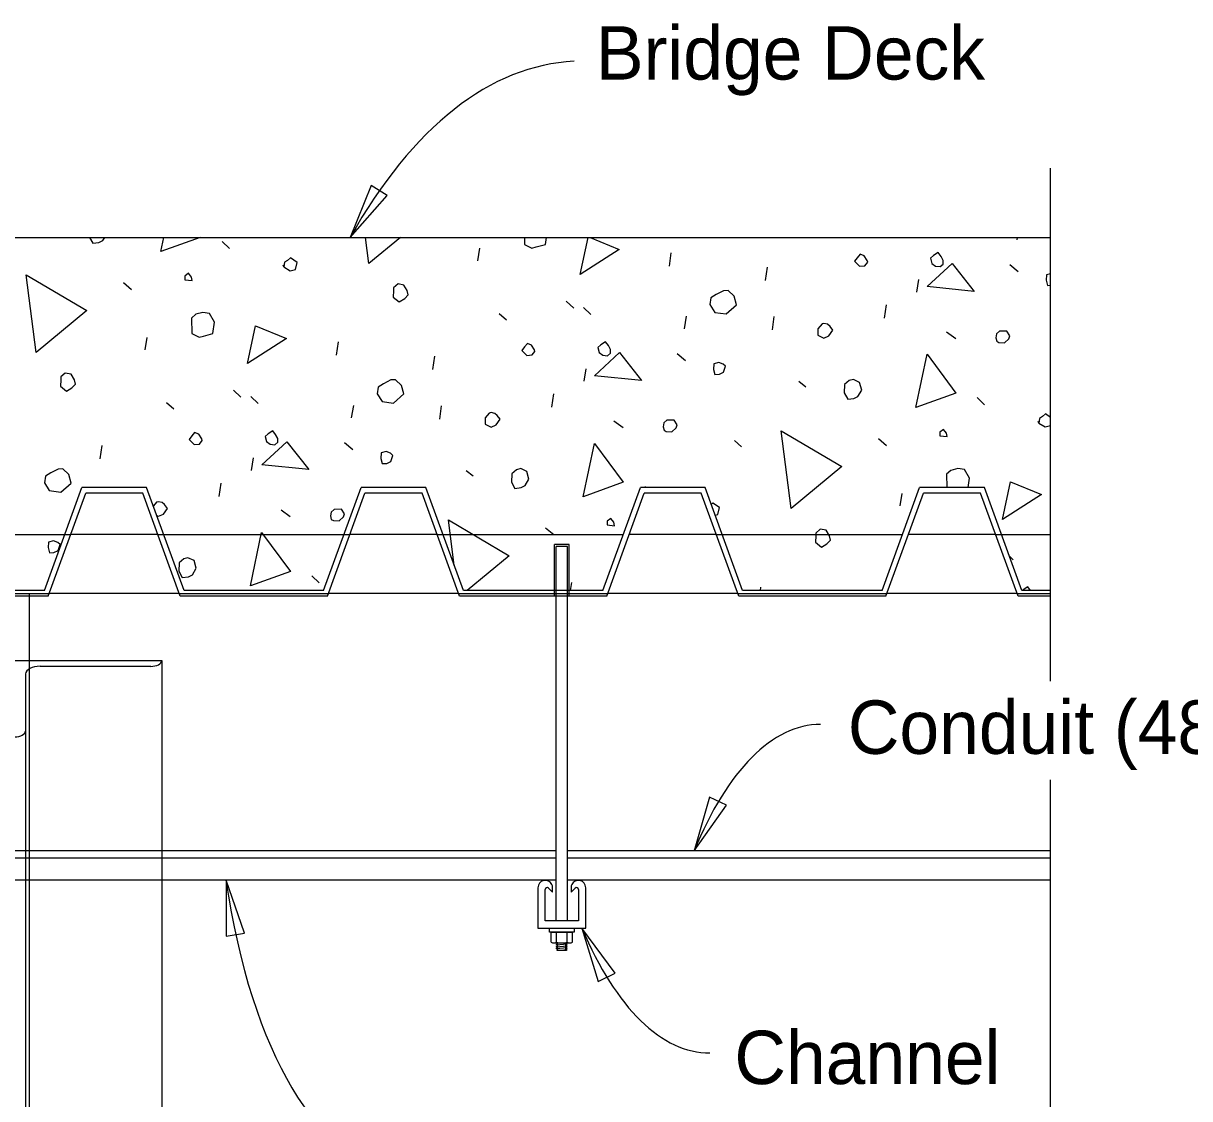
# Model space of a CAD drawing. Extents: x 0 to 30.8, y 0 to 21.2.
# Drawn here: x 17.853 to 21.155, y 6.096 to 9.141 of the extents above; entities that cross this region are included whole.
import ezdxf

# ---------------------------------------------------------------- set-up
doc = ezdxf.new("R2010")
doc.units = 0
for name, color, linetype in [('Dimension', 7, 'Continuous'), ('Lighting', 7, 'Continuous'), ('Lighting_h', 7, 'Continuous'), ('Miscellaneous', 7, 'Continuous'), ('SteelGirder', 7, 'Continuous'), ('SteelGirder_h', 7, 'Continuous'), ('SupstrConc', 7, 'Continuous'), ('TextStructures', 7, 'Continuous')]:
    doc.layers.add(name, color=color, linetype=linetype)

msp = doc.modelspace()

# ---------------------------------------------------------------- linework, layer by layer
at = {"layer": 'Dimension'}
for points in [[(20.7608, 7.2784), (20.7608, 8.7314)], [(20.7608, 1.0713), (20.7608, 4.831), (20.6833, 4.831), (20.7608, 4.8647), (20.8383, 4.8985), (20.7608, 4.8985), (20.7608, 6.9989)]]:
    msp.add_lwpolyline(points, dxfattribs=at)
for points in [[(18.7785, 8.5353), (18.8832, 8.6542), (18.8382, 8.682)], [(19.7521, 6.798), (19.8434, 6.9274), (19.7957, 6.9503)], [(18.4271, 6.7147), (18.4271, 6.5563), (18.4793, 6.5651)], [(19.4346, 6.5793), (19.481, 6.4278), (19.5283, 6.4515)]]:
    msp.add_lwpolyline(points, close=True, dxfattribs=at)
for centre, major_axis, ratio, start_param, end_param in [((19.5236, 6.6665), (0.1111, -2.3674), 0.464296, 3.141604, 3.781059), ((20.1176, 5.9751), (0.0076, -1.1813), 0.426092, 3.141637, 3.939024), ((18.903, 7.0853), (0.0076, -1.1813), 0.426092, 5.02876, 6.283138), ((19.7893, 7.4071), (0.0076, -1.1813), 0.426092, 5.486066, 6.283138)]:
    msp.add_ellipse(centre, major_axis=major_axis, ratio=ratio, start_param=start_param, end_param=end_param, dxfattribs=at)
at = {"layer": 'Lighting'}
for p, q in [((19.3621, 6.798), (18.2451, 6.798)), ((19.3621, 6.7772), (18.2451, 6.7772)), ((20.7608, 6.798), (19.3933, 6.798)), ((20.7608, 6.7772), (19.3933, 6.7772)), ((19.3621, 6.7147), (18.2451, 6.7147)), ((19.3516, 6.6987), (19.3494, 6.7031)), ((20.7608, 6.7147), (19.3933, 6.7147)), ((19.4059, 6.7031), (19.4038, 6.6987)), ((19.31, 6.6939), (19.31, 6.5793)), ((19.3308, 6.6001), (19.3308, 6.6891)), ((19.3397, 6.6928), (19.3516, 6.6808)), ((19.3516, 6.6808), (19.3516, 6.6987)), ((19.4038, 6.6987), (19.4038, 6.6808)), ((19.4038, 6.6808), (19.4157, 6.6928)), ((19.4246, 6.6891), (19.4246, 6.6001)), ((19.4454, 6.5793), (19.4454, 6.6939)), ((19.31, 6.5793), (19.4454, 6.5793)), ((19.4246, 6.6001), (19.3308, 6.6001))]:
    msp.add_line(p, q, dxfattribs=at)
for centre, radius, start, end in [((19.3308, 6.6939), 0.0208, 26.1794, 179.9999), ((19.4246, 6.6939), 0.0208, 0.0001, 153.8206), ((19.336, 6.6891), 0.0052, 45, 180), ((19.4194, 6.6891), 0.0052, 360, 135)]:
    msp.add_arc(centre, radius, start, end, dxfattribs=at)
at = {"layer": 'Lighting_h'}
for p, q in [((18.2451, 6.798), (17.6513, 6.798)), ((18.2451, 6.7772), (17.6513, 6.7772)), ((18.2451, 6.7147), (17.6513, 6.7147))]:
    msp.add_line(p, q, dxfattribs=at)
at = {"layer": 'Miscellaneous'}
for p, q in [((18.4159, 8.5237), (18.4369, 8.5034)), ((20.6663, 8.5288), (20.6674, 8.5353)), ((19.1397, 8.4692), (19.1458, 8.5045)), ((19.6821, 8.4541), (19.6875, 8.4917)), ((20.6462, 8.4587), (20.6696, 8.4391)), ((19.9545, 8.4132), (19.9599, 8.4508)), ((18.1365, 8.4074), (18.1599, 8.3878)), ((20.3825, 8.3803), (20.3886, 8.4156)), ((19.3902, 8.3551), (19.4112, 8.3349)), ((19.4391, 8.3372), (19.46, 8.3169)), ((20.291, 8.3066), (20.2964, 8.3443)), ((19.2004, 8.3198), (19.2207, 8.302)), ((19.7245, 8.2765), (19.7306, 8.3118)), ((19.9738, 8.2734), (19.9792, 8.3111)), ((20.4669, 8.2683), (20.4927, 8.2494)), ((18.1979, 8.2168), (18.204, 8.2521)), ((18.7403, 8.2017), (18.7457, 8.2394)), ((19.0127, 8.1608), (19.0181, 8.1985)), ((19.7045, 8.2064), (19.7278, 8.1868)), ((19.4408, 8.128), (19.4468, 8.1633)), ((20.049, 8.1279), (20.0687, 8.1125)), ((18.4485, 8.1028), (18.4694, 8.0825)), ((19.3492, 8.0543), (19.3547, 8.092)), ((18.2586, 8.0675), (18.279, 8.0496)), ((18.4973, 8.0848), (18.5182, 8.0646)), ((18.7827, 8.0241), (18.7888, 8.0594)), ((19.032, 8.021), (19.0374, 8.0587)), ((20.5531, 8.0818), (20.5741, 8.0615)), ((19.5251, 8.016), (19.5509, 7.997)), ((19.8663, 7.9599), (19.8866, 7.942)), ((20.2737, 7.9655), (20.2971, 7.9459)), ((18.0709, 7.9085), (18.0763, 7.9461)), ((18.7627, 7.9541), (18.786, 7.9344)), ((18.499, 7.8756), (18.5051, 7.9109)), ((19.1072, 7.8756), (19.1269, 7.8601)), ((17.9129, 7.5353), (18.0191, 7.827)), ((18.2024, 7.827), (18.0191, 7.827)), ((18.3086, 7.5353), (18.2024, 7.827)), ((18.4074, 7.8019), (18.4129, 7.8396)), ((18.7034, 7.5353), (18.8096, 7.827)), ((18.9929, 7.827), (18.8096, 7.827)), ((19.0991, 7.5353), (18.9929, 7.827)), ((19.4938, 7.5353), (19.6, 7.827)), ((19.7833, 7.827), (19.6, 7.827)), ((19.6113, 7.8295), (19.6138, 7.827)), ((19.8895, 7.5353), (19.7833, 7.827)), ((20.2843, 7.5353), (20.3904, 7.827)), ((20.5737, 7.827), (20.3904, 7.827)), ((20.6799, 7.5353), (20.5737, 7.827)), ((17.9239, 7.5197), (18.03, 7.8114)), ((18.1915, 7.8114), (18.03, 7.8114)), ((18.2977, 7.5197), (18.1915, 7.8114)), ((18.7143, 7.5197), (18.8205, 7.8114)), ((18.9819, 7.8114), (18.8205, 7.8114)), ((19.0881, 7.5197), (18.9819, 7.8114)), ((19.5047, 7.5197), (19.6109, 7.8114)), ((19.7724, 7.8114), (19.6109, 7.8114)), ((19.8786, 7.5197), (19.7724, 7.8114)), ((20.2952, 7.5197), (20.4014, 7.8114)), ((20.3351, 7.7749), (20.3412, 7.8102)), ((20.5628, 7.8114), (20.4014, 7.8114)), ((20.669, 7.5197), (20.5628, 7.8114)), ((18.5833, 7.7636), (18.6091, 7.7447)), ((19.3319, 7.7132), (19.3553, 7.6936)), ((20.6442, 7.6335), (20.6554, 7.6226)), ((18.6696, 7.5771), (18.6905, 7.5568)), ((17.9129, 7.5353), (17.5182, 7.5353)), ((18.7034, 7.5353), (18.3086, 7.5353)), ((19.4938, 7.5353), (19.0991, 7.5353)), ((19.4025, 7.5353), (19.4063, 7.5579)), ((20.2843, 7.5353), (19.8895, 7.5353)), ((19.9397, 7.5353), (19.9412, 7.5451)), ((20.7608, 7.5353), (20.6799, 7.5353)), ((17.9239, 7.5197), (17.5073, 7.5197)), ((18.7143, 7.5197), (18.2977, 7.5197)), ((19.5047, 7.5197), (19.0881, 7.5197)), ((20.2952, 7.5197), (19.8786, 7.5197)), ((20.7608, 7.5197), (20.669, 7.5197))]:
    msp.add_line(p, q, dxfattribs=at)
for points in [[(18.0405, 8.5353), (18.0497, 8.5188), (18.0673, 8.5209), (18.0787, 8.5265), (18.0838, 8.5353)], [(18.2424, 8.4953), (18.2508, 8.5353)], [(18.3537, 8.5353), (18.2424, 8.4953)], [(18.8312, 8.4616), (18.8218, 8.5353)], [(18.9206, 8.5353), (18.8312, 8.4616)], [(19.2717, 8.5353), (19.2723, 8.5151), (19.2931, 8.5051), (19.3052, 8.5084), (19.3318, 8.5155), (19.3344, 8.5353)], [(19.4296, 8.4304), (19.4522, 8.5353)], [(19.4579, 8.5353), (19.54, 8.5014), (19.4296, 8.4304)], [(20.2064, 8.4677), (20.2206, 8.4534), (20.2357, 8.4549), (20.2435, 8.4647), (20.2422, 8.4695), (20.2335, 8.4827), (20.2219, 8.4874), (20.2141, 8.4776), (20.2064, 8.4677)], [(20.4254, 8.4617), (20.4353, 8.454), (20.4486, 8.4524), (20.457, 8.4598), (20.4568, 8.4701), (20.4512, 8.4815), (20.4431, 8.4923), (20.4299, 8.4836), (20.4216, 8.4762), (20.4254, 8.4617)], [(18.5906, 8.4515), (18.6089, 8.4408), (18.6234, 8.4447), (18.6286, 8.4642), (18.6095, 8.4772), (18.6012, 8.4698), (18.5922, 8.4648), (18.5906, 8.4515), (18.5893, 8.4563)], [(20.412, 8.396), (20.4825, 8.4615), (20.545, 8.3825), (20.412, 8.396)], [(17.8894, 8.2092), (17.8614, 8.4295), (18.0335, 8.3281), (17.8894, 8.2092)], [(18.3104, 8.4152), (18.3317, 8.4131), (18.3291, 8.4228), (18.321, 8.4336), (18.3102, 8.4255), (18.3104, 8.4152)], [(20.7608, 8.4325), (20.7498, 8.4296), (20.7489, 8.4138)], [(18.901, 8.3845), (18.9007, 8.3663), (18.9173, 8.3526), (18.9329, 8.362), (18.943, 8.3725), (18.9398, 8.3846), (18.9304, 8.4002), (18.914, 8.4035), (18.9014, 8.3924), (18.901, 8.3845)], [(20.7489, 8.4138), (20.7527, 8.3993), (20.7608, 8.3998)], [(19.7967, 8.345), (19.8104, 8.3228), (19.8427, 8.3185), (19.8719, 8.3444), (19.8655, 8.3686), (19.8482, 8.3847), (19.8355, 8.3839), (19.815, 8.3732), (19.7994, 8.3638), (19.7967, 8.345)], [(18.3292, 8.3064), (18.3306, 8.2627), (18.3513, 8.2528), (18.3634, 8.256), (18.39, 8.2631), (18.3943, 8.2953), (18.3799, 8.32), (18.3611, 8.3227), (18.3418, 8.3175), (18.3292, 8.3064)], [(20.1023, 8.2768), (20.102, 8.2586), (20.1197, 8.2504), (20.1336, 8.2567), (20.1448, 8.2726), (20.1368, 8.2834), (20.13, 8.2894), (20.119, 8.2916), (20.1142, 8.2903), (20.1023, 8.2768)], [(18.4878, 8.178), (18.5109, 8.2852), (18.5982, 8.249), (18.4878, 8.178)], [(20.6086, 8.2416), (20.6148, 8.2381), (20.6306, 8.2371), (20.6431, 8.2483), (20.646, 8.2568), (20.6373, 8.27), (20.6167, 8.2697), (20.6083, 8.2622), (20.6061, 8.2513), (20.6086, 8.2416)], [(19.2646, 8.2154), (19.2788, 8.2011), (19.294, 8.2025), (19.3017, 8.2124), (19.3004, 8.2172), (19.2917, 8.2304), (19.2801, 8.235), (19.2724, 8.2252), (19.2646, 8.2154)], [(19.4837, 8.2094), (19.4935, 8.2016), (19.5069, 8.2), (19.5152, 8.2075), (19.5151, 8.2178), (19.5094, 8.2292), (19.5013, 8.24), (19.4881, 8.2313), (19.4798, 8.2238), (19.4837, 8.2094)], [(19.4702, 8.1436), (19.5407, 8.2091), (19.6033, 8.1301), (19.4702, 8.1436)], [(20.3796, 8.0534), (20.4116, 8.2043), (20.4929, 8.0941), (20.3796, 8.0534)], [(19.8071, 8.1614), (19.811, 8.1469), (19.8237, 8.1478), (19.8351, 8.1534), (19.8409, 8.1705), (19.8341, 8.1764), (19.8225, 8.1811), (19.808, 8.1772), (19.8071, 8.1614)], [(17.9592, 8.1322), (17.9589, 8.114), (17.9755, 8.1003), (17.9911, 8.1097), (18.0012, 8.1201), (17.998, 8.1322), (17.9886, 8.1478), (17.9722, 8.1512), (17.9597, 8.1401), (17.9592, 8.1322)], [(18.8549, 8.0927), (18.8687, 8.0704), (18.9009, 8.0661), (18.9302, 8.0921), (18.9237, 8.1162), (18.9064, 8.1323), (18.8937, 8.1315), (18.8733, 8.1209), (18.8577, 8.1115), (18.8549, 8.0927)], [(20.1783, 8.1186), (20.1769, 8.0949), (20.1869, 8.0769), (20.2045, 8.079), (20.2159, 8.0846), (20.2265, 8.103), (20.2207, 8.1247), (20.203, 8.1329), (20.1909, 8.1297), (20.1783, 8.1186)], [(19.1605, 8.0244), (19.1602, 8.0062), (19.1779, 7.998), (19.1918, 8.0043), (19.203, 8.0203), (19.195, 8.0311), (19.1882, 8.037), (19.1772, 8.0393), (19.1724, 8.038), (19.1605, 8.0244)], [(20.7608, 8.0257), (20.7467, 8.0353), (20.7384, 8.0279), (20.7294, 8.0229), (20.7278, 8.0095), (20.7265, 8.0144)], [(19.6669, 7.9893), (19.673, 7.9857), (19.6888, 7.9848), (19.7013, 7.9959), (19.7042, 8.0045), (19.6955, 8.0177), (19.6749, 8.0173), (19.6665, 8.0099), (19.6643, 7.9989), (19.6669, 7.9893)], [(20.4476, 7.9733), (20.4689, 7.9712), (20.4663, 7.9809), (20.4582, 7.9917), (20.4474, 7.9836), (20.4476, 7.9733)], [(20.7278, 8.0095), (20.7461, 7.9989), (20.7606, 8.0028), (20.7608, 8.0035)], [(18.3229, 7.963), (18.3371, 7.9487), (18.3522, 7.9502), (18.3599, 7.96), (18.3586, 7.9648), (18.3499, 7.978), (18.3383, 7.9827), (18.3306, 7.9729), (18.3229, 7.963)], [(18.5419, 7.957), (18.5517, 7.9493), (18.5651, 7.9477), (18.5735, 7.9551), (18.5733, 7.9654), (18.5676, 7.9768), (18.5596, 7.9876), (18.5464, 7.9789), (18.538, 7.9715), (18.5419, 7.957)], [(20.0266, 7.7673), (19.9986, 7.9876), (20.1707, 7.8862), (20.0266, 7.7673)], [(18.5284, 7.8913), (18.5989, 7.9568), (18.6615, 7.8778), (18.5284, 7.8913)], [(18.8653, 7.9091), (18.8692, 7.8946), (18.8819, 7.8954), (18.8933, 7.9011), (18.8991, 7.9181), (18.8923, 7.9241), (18.8807, 7.9287), (18.8663, 7.9249), (18.8653, 7.9091)], [(19.4378, 7.8011), (19.4698, 7.952), (19.5511, 7.8418), (19.4378, 7.8011)], [(17.9132, 7.8403), (17.9269, 7.8181), (17.9591, 7.8138), (17.9884, 7.8398), (17.9819, 7.8639), (17.9647, 7.88), (17.9519, 7.8792), (17.9315, 7.8685), (17.9159, 7.8592), (17.9132, 7.8403)], [(19.2366, 7.8662), (19.2351, 7.8425), (19.2451, 7.8245), (19.2627, 7.8266), (19.2741, 7.8323), (19.2847, 7.8506), (19.2789, 7.8724), (19.2612, 7.8806), (19.2491, 7.8773), (19.2366, 7.8662)], [(20.528, 7.827), (20.5315, 7.8534), (20.5171, 7.878), (20.4983, 7.8808), (20.479, 7.8756), (20.4664, 7.8645)], [(20.4664, 7.8645), (20.4676, 7.827)], [(20.625, 7.7361), (20.6481, 7.8433), (20.7354, 7.8071), (20.625, 7.7361)], [(18.2312, 7.748), (18.2362, 7.7457), (18.25, 7.752), (18.2613, 7.7679), (18.2532, 7.7787), (18.2464, 7.7847), (18.2355, 7.7869), (18.2306, 7.7856), (18.2214, 7.775)], [(18.7251, 7.7369), (18.7312, 7.7334), (18.747, 7.7324), (18.7595, 7.7436), (18.7624, 7.7521), (18.7537, 7.7653), (18.7331, 7.765), (18.7247, 7.7575), (18.7225, 7.7466), (18.7251, 7.7369)], [(19.8119, 7.7486), (19.8189, 7.7505), (19.824, 7.77), (19.805, 7.783), (19.8007, 7.7792)], [(19.0732, 7.6063), (19.0568, 7.7352), (19.2289, 7.6338), (19.1094, 7.5353)], [(19.5058, 7.721), (19.5271, 7.7189), (19.5245, 7.7285), (19.5164, 7.7393), (19.5057, 7.7313), (19.5058, 7.721)], [(18.496, 7.5487), (18.528, 7.6996), (18.6093, 7.5894), (18.496, 7.5487)], [(20.0964, 7.6903), (20.0961, 7.6721), (20.1127, 7.6584), (20.1283, 7.6677), (20.1384, 7.6782), (20.1352, 7.6903), (20.1258, 7.7059), (20.1094, 7.7093), (20.0969, 7.6981), (20.0964, 7.6903)], [(17.9235, 7.6567), (17.9274, 7.6422), (17.9401, 7.6431), (17.9516, 7.6487), (17.9573, 7.6658), (17.9506, 7.6717), (17.939, 7.6764), (17.9245, 7.6725), (17.9235, 7.6567)], [(18.2948, 7.6139), (18.2934, 7.5902), (18.3034, 7.5722), (18.3209, 7.5743), (18.3323, 7.5799), (18.3429, 7.5983), (18.3371, 7.62), (18.3194, 7.6282), (18.3073, 7.625), (18.2948, 7.6139)], [(20.7046, 7.5353), (20.6968, 7.5457), (20.6836, 7.537), (20.6816, 7.5353)]]:
    msp.add_lwpolyline(points, dxfattribs=at)
at = {"layer": 'SteelGirder'}
for p, q in [((18.2342, 7.694), (17.9873, 7.694)), ((19.0247, 7.694), (18.7778, 7.694)), ((19.8151, 7.694), (19.5682, 7.694)), ((20.6056, 7.694), (20.3586, 7.694)), ((19.3985, 7.6655), (19.3569, 7.6655)), ((19.3569, 7.5197), (19.3569, 7.6655)), ((19.3621, 6.6001), (19.3621, 7.6603)), ((19.3933, 7.6603), (19.3621, 7.6603)), ((19.3933, 6.6001), (19.3933, 7.6603)), ((19.3985, 7.5197), (19.3985, 7.6655)), ((17.8701, 7.5273), (17.8701, 7.3368)), ((18.2949, 7.5273), (17.9266, 7.5273)), ((19.0854, 7.5273), (18.7171, 7.5273)), ((19.8758, 7.5273), (19.5075, 7.5273)), ((20.6662, 7.5273), (20.298, 7.5273)), ((17.8284, 7.3368), (18.2451, 7.3368)), ((18.2451, 7.3368), (18.2451, 2.4661)), ((17.8596, 7.2991), (17.8596, 7.1373)), ((18.2138, 7.3206), (17.9013, 7.3206)), ((17.8596, 7.1373), (17.8596, 2.2664)), ((19.3476, 6.5398), (19.3476, 6.5682)), ((19.3476, 6.5682), (19.4077, 6.5682)), ((19.3551, 6.5376), (19.4002, 6.5376)), ((19.362, 6.537), (19.3686, 6.5376)), ((19.362, 6.537), (19.363, 6.5376)), ((19.3626, 6.5398), (19.3626, 6.5682)), ((19.388, 6.5366), (19.3896, 6.5376)), ((19.3927, 6.5398), (19.3927, 6.5682)), ((19.4077, 6.5398), (19.4077, 6.5682)), ((19.3673, 6.5348), (19.362, 6.537)), ((19.362, 6.5318), (19.3673, 6.5348)), ((19.362, 6.5318), (19.3932, 6.5345)), ((19.3673, 6.5296), (19.362, 6.5318)), ((19.362, 6.5266), (19.3673, 6.5296)), ((19.362, 6.5266), (19.3932, 6.5293)), ((19.3673, 6.5244), (19.362, 6.5266)), ((19.362, 6.5214), (19.3673, 6.5244)), ((19.362, 6.5214), (19.3932, 6.5241)), ((19.3673, 6.5192), (19.362, 6.5214)), ((19.3638, 6.5173), (19.3673, 6.5192)), ((19.3638, 6.5173), (19.3904, 6.5173)), ((19.3739, 6.5173), (19.3932, 6.5189)), ((19.3932, 6.5345), (19.388, 6.5366)), ((19.388, 6.5314), (19.3932, 6.5345)), ((19.3932, 6.5293), (19.388, 6.5314)), ((19.388, 6.5263), (19.3932, 6.5293)), ((19.3932, 6.5241), (19.388, 6.5263)), ((19.388, 6.521), (19.3932, 6.5241)), ((19.3932, 6.5189), (19.388, 6.521)), ((19.3904, 6.5173), (19.3932, 6.5189))]:
    msp.add_line(p, q, dxfattribs=at)
msp.add_lwpolyline([(19.4129, 6.5793), (19.4129, 6.5682), (19.3424, 6.5682), (19.3424, 6.5793)], close=True, dxfattribs=at)
for centre, radius, start, end in [((19.3551, 6.5514), 0.0138, 236.9791, 303.0209), ((19.3776, 6.5894), 0.0519, 253.1396, 286.8604), ((19.4002, 6.5514), 0.0138, 236.9791, 303.0209)]:
    msp.add_arc(centre, radius, start, end, dxfattribs=at)
for centre, major_axis in [((18.2138, 7.3368), (0.0313, 0)), ((17.9013, 7.2991), (-0.0417, 0)), ((17.8284, 7.1373), (0.0312, 0))]:
    msp.add_ellipse(centre, major_axis=major_axis, ratio=0.5176, start_param=4.712389, end_param=6.283185, dxfattribs=at)
at = {"layer": 'SteelGirder_h'}
for p, q in [((17.4438, 7.694), (17.9873, 7.694)), ((18.2342, 7.694), (18.7778, 7.694)), ((19.0247, 7.694), (19.5516, 7.694)), ((19.8151, 7.694), (20.342, 7.694)), ((20.6056, 7.694), (20.7608, 7.694)), ((17.5045, 7.5273), (17.9266, 7.5273)), ((18.2949, 7.5273), (18.7171, 7.5273)), ((19.0854, 7.5273), (19.1583, 7.5273)), ((19.0854, 7.5273), (19.5075, 7.5273)), ((19.8758, 7.5273), (19.9488, 7.5273)), ((19.8758, 7.5273), (20.298, 7.5273)), ((20.6662, 7.5273), (20.7392, 7.5273)), ((20.6662, 7.5273), (20.7608, 7.5273)), ((17.8701, 7.3368), (17.8701, 2.4426))]:
    msp.add_line(p, q, dxfattribs=at)
at = {"layer": 'SupstrConc'}
msp.add_line((13.7516, 8.5353), (20.7608, 8.5353), dxfattribs=at)

# ---------------------------------------------------------------- texts
at = {"layer": 'TextStructures'}
for s, p in [('Bridge Deck', (19.4743, 8.9822)), ('Conduit (480V)', (20.1873, 7.0728)), ('Channel', (19.8662, 6.1377))]:
    msp.add_text(s, height=0.1512, dxfattribs=at).set_placement(p)

doc.saveas('drawing.dxf')
